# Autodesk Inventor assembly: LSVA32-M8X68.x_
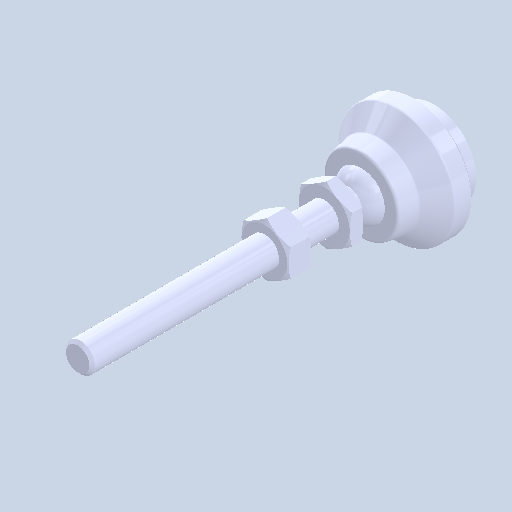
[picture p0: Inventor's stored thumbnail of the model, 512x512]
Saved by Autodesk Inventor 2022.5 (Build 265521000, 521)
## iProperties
Created: 2024-08
Part Number: LSVA32-M8X68.x_
Document SubType Name: Assembly
Designer: ImaoCorp
Author: ImaoCorp
Sending System: SOLIDWORKS 2022-2022290
MC: AMD64
MC_MODEL: Intel64 Family 6 Model 60 Stepping 3, GenuineIntel
OS: Windows_NT
FRU: Parasolid Version 33.1, build 260,  4-25-2022
FORMAT: text
GUISE: transmit
KEY: FILELSVA32-M8X68.x_t
DATE: Fri Aug 23 16:07:07 2024
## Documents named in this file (4)
- X:\14_SW2022-Inv2022\06_2024-10新製品(SME)\ELS_データ\l\lsva32-m8x68\LSVA32-M8X68.x_.iam
- X:\14_SW2022-Inv2022\06_2024-10新製品(SME)\ELS_データ\l\lsva32-m8x68\LSVA32-M8X68_01.ipt
- X:\14_SW2022-Inv2022\06_2024-10新製品(SME)\ELS_データ\l\lsva32-m8x68\LSVA32-M8X68_02.ipt
- X:\14_SW2022-Inv2022\06_2024-10新製品(SME)\ELS_データ\l\lsva32-m8x68\LSVA32-M8X68_03.ipt
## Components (3 placed, 3 different names)
1. LSVA32-M8X68_01
2. LSVA32-M8X68_02
3. LSVA32-M8X68_03
